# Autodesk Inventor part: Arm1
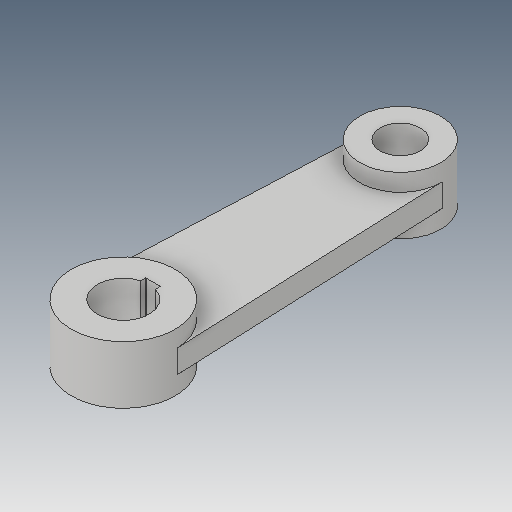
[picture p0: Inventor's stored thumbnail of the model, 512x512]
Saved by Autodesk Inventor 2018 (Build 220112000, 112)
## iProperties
Created: 2016-05
Part Number: Arm1
Material: Generic
Document SubType Name: Modeling
Designer: CADCIM
Density: 1 g/cm^3
Appearance: Default
Author: CADCIM
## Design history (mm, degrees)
sketch "Sketch1"
  geometry: C1 r 56.25 at (0, 0); C2 r 28 at (0, 0); C3 r 43.75 at (0, -300); C4 r 21.75 at (0, -300); 1 further point
  constraints: 4 centre point, 3 coincident
  dimensions: "d0" = 112.5 diameter of C1; "d1" = 56 diameter of C2; "d2" = 87.5 diameter of C3; "d3" = 43.5 diameter of C4; "d4" = 300 distance of C4.centre C2.centre
extrude "Extrusion1" new body sketch "Sketch1" stored distance "d5" = 62.5; taper "d6" = 0 deg
sketch "Sketch2"
  geometry: L1 (56.201, -2.344)-(43.712, -301.823); L2 (-56.201, -2.344)-(-43.712, -301.823); A1 r 56.25 centre (0, 0) between (-56.201, -2.344) and (56.201, -2.344); A2 r 43.75 centre (0, -300) between (43.712, -301.823) and (-43.712, -301.823); 3 further points
  constraints: 4 end point, 4 point on circle, 2 centre point, 2 coincident
extrude "Extrusion2" join sketch "Sketch2" stored distance "d7" = 25; taper "d8" = 0 deg
sketch "Sketch3"
  geometry: L1 (0, 0)-(0, 99.622); L2 (-8, 26.833)-(8, 26.833); L3 (8, 26.833)-(8, 32.3); L4 (8, 32.3)-(-8, 32.3); L5 (-8, 32.3)-(-8, 26.833); L6 (0, 0)-(0, -28); A1 r 28 centre (0, 0) between (-8, 26.833) and (8, 26.833) reference
  constraints: 12 end point, 3 point on circle, 2 parallel, 2 vertical, 1 horizontal, 1 perpendicular, 1 other
  dimensions: "d10" = 16 distance of L3.end L4.end; "d11" = 60.3 distance from line of L4 L6.end
extrude "Extrusion3" cut sketch "Sketch3" extent not by distance; stored distance "d12" = 25; taper "d13" = 0 deg
fillet "Fillet1" dims "d14" = 0.4
body "Solid1"
